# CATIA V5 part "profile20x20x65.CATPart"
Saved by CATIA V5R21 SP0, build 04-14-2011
Part number: 65
Bounding box of the stored display mesh (mm): x -24.289 to -4.289, y -1.335 to 18.665, z 0 to 65
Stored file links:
  C:\Users\2027.DESARCY-LEMIE30\Desktop\V15(20.03.2023)\profile20x20x65.CATPart
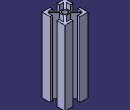
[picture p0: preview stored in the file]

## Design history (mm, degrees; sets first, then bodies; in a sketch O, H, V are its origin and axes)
Body1 (main body)
  Sketch1 on xy-plane, origin (0, 0, 0), H (1, 0, 0), V (0, 1, 0)
    point P1 (-17.2892, 11.6647)
    line L1 (-16.2892, 11.6647) -> (-12.2892, 11.6647)
    point P2 (-11.2892, 11.6647)
    line L2 (-11.2892, 10.6647) -> (-11.2892, 6.6647)
    point P3 (-11.2892, 5.6647)
    line L3 (-12.2892, 5.6647) -> (-16.2892, 5.6647)
    point P4 (-17.2892, 5.6647)
    line L4 (-17.2892, 6.6647) -> (-17.2892, 10.6647)
    point P5 (-24.2892, 18.6647)
    point P6 (-4.2892, 18.6647)
    point P7 (-4.2892, -1.3353)
    line L5 (-11.1892, 18.6647) -> (-11.1892, 16.6647)
    point P8 (-11.1892, 18.6647)
    point P10 (-11.1892, 18.6647)
    point P11 (-17.3892, 18.6647)
    line L6 (-17.3892, 18.6647) -> (-17.3892, 16.6647)
    point P12 (-17.3892, 18.6647)
    line L7 (-11.1892, 18.6647) -> (-4.2892, 18.6647)
    point P14 (-11.1892, 18.6647)
    point P15 (-4.2892, 18.6647)
    point P16 (-11.1892, -1.3353)
    point P17 (-17.3892, -1.3353)
    line L8 (-17.3892, -1.3353) -> (-17.3892, 0.6647)
    point P18 (-17.3892, -1.3353)
    line L9 (-11.1892, -1.3353) -> (-11.1892, 0.6647)
    point P20 (-11.1892, -1.3353)
    line L10 (-24.2892, -1.3353) -> (-17.3892, -1.3353)
    point P22 (-24.2892, -1.3353)
    point P23 (-17.3892, -1.3353)
    line L11 (-11.1892, -1.3353) -> (-4.2892, -1.3353)
    point P24 (-11.1892, -1.3353)
    point P25 (-4.2892, -1.3353)
    line L12 (-24.2892, 18.6647) -> (-17.3892, 18.6647)
    point P26 (-24.2892, 18.6647)
    point P27 (-17.3892, 18.6647)
    point P28 (-4.2892, 5.5647)
    point P29 (-4.2892, 11.7647)
    line L13 (-6.2892, 11.7647) -> (-4.2892, 11.7647)
    point P31 (-4.2892, 11.7647)
    line L14 (-4.2892, 5.5647) -> (-6.2892, 5.5647)
    point P32 (-4.2892, 5.5647)
    point P34 (-24.2892, 5.5647)
    point P35 (-24.2892, 11.7647)
    line L15 (-24.2892, 11.7647) -> (-22.2892, 11.7647)
    point P36 (-24.2892, 11.7647)
    line L16 (-24.2892, 5.5647) -> (-22.2892, 5.5647)
    point P38 (-24.2892, 5.5647)
    line L17 (-4.2892, 18.6647) -> (-4.2892, 11.7647)
    point P40 (-4.2892, 18.6647)
    point P41 (-4.2892, 11.7647)
    line L18 (-24.2892, 18.6647) -> (-24.2892, 11.7647)
    point P42 (-24.2892, 18.6647)
    point P43 (-24.2892, 11.7647)
    line L19 (-24.2892, -1.3353) -> (-24.2892, 5.5647)
    point P44 (-24.2892, -1.3353)
    point P45 (-24.2892, 5.5647)
    line L20 (-4.2892, -1.3353) -> (-4.2892, 5.5647)
    point P46 (-4.2892, -1.3353)
    point P47 (-4.2892, 5.5647)
    line L21 (-22.2892, 5.5647) -> (-22.2892, 1.6647)
    line L22 (-21.2892, 0.6647) -> (-17.3892, 0.6647)
    line L23 (-6.2892, 5.5647) -> (-6.2892, 1.6647)
    line L24 (-11.1892, 0.6647) -> (-7.2892, 0.6647)
    line L25 (-11.1892, 16.6647) -> (-7.2892, 16.6647)
    line L26 (-6.2892, 15.6647) -> (-6.2892, 11.7647)
    line L27 (-17.3892, 16.6647) -> (-21.2892, 16.6647)
    line L28 (-22.2892, 15.6647) -> (-22.2892, 11.7647)
    point P48 (-16.2892, 11.6647)
    point P49 (-17.2892, 10.6647)
    point P50 (-17.2892, 6.6647)
    point P52 (-11.2892, 6.6647)
    point P53 (-11.2892, 10.6647)
    point P54 (-12.2892, 11.6647)
    point P55 (-12.2892, 5.6647)
    line L29 (-16.2892, 11.6647) -> (-21.2892, 16.6647)
    line L30 (-17.2892, 10.6647) -> (-22.2892, 15.6647)
    line L31 (-12.2892, 11.6647) -> (-7.2892, 16.6647)
    line L32 (-16.2892, 5.6647) -> (-21.2892, 0.6647)
    line L33 (-17.2892, 6.6647) -> (-22.2892, 1.6647)
    line L34 (-12.2892, 5.6647) -> (-7.2892, 0.6647)
    line L35 (-11.2892, 6.6647) -> (-6.2892, 1.6647)
    line L36 (-11.2892, 10.6647) -> (-6.2892, 15.6647)
    length L5 = 2
    distance P10 P6 = 6.9
    length L6 = 2
    length L8 = 2
    length L9 = 2
    distance P7 P28 = 6.9
    distance P6 P29 = 6.9
    length L13 = 2
    length L14 = 2
    length L15 = 2
    distance P5 P42 = 0
    length L11 = 6.9
    distance P46 P7 = 0
    distance P1 P48 = 1
    distance P49 P1 = 1
    distance P4 P50 = 1
    distance P54 P2 = 1
    distance P2 P3 = 6
    distance P1 P2 = 6
    horizontal: L1 H, L3 H, L7 H, L10 H, L11 H, L12 H, L13 H, L14 H, L15 H, L16 H, L22 H, L24 H, L25 H, L27 H
    vertical: L2 V, L4 V, L5 V, L6 V, L8 V, L9 V, L17 V, L18 V, L19 V, L20 V, L21 V, L23 V, L26 V, L28 V
    coincidence: P10 P8, P11 P12, P6 P15, P8 P14, P16 L5, P17 L6, P17 P18, P16 P20, P23 L8, P24 L9, P20 P24, P27 L6, P5 P26, P29 P31, P28 P32, P34 L14, P35 L13, P34 P38, P35 P36, P40 L7, P41 L13, P6 P40, P42 L7, P43 L13, P44 L11, P45 L14, P38 P45, P46 L11, P47 L14, P49 L4, P50 L4, P52 L2, P53 L2, P55 L3, P22 P44, P25 P46
    fix: P34, P12, P5, P36, P55
  Pad1: profile Sketch1, direction (0, 0, 1), length 65
  Sketch2 on end face of Pad1, origin (0, 0, 65), H (1, 0, 0), V (0, 1, 0)
    circle A1 centre (-14.2892, 8.6647) radius 2.5
    point P1 (-14.2892, 8.6647)
    reference projected line E1 (-12.2892, 11.6647) -> (-16.2892, 11.6647) from edge [face of Pad1 from Sketch1.L1 | end face of Pad1]
    reference projected line E2 (-11.2892, 6.6647) -> (-11.2892, 10.6647) from edge [face of Pad1 from Sketch1.L2 | end face of Pad1]
    radius A1 = 2.5
    distance P1 E1 = 3
    distance P1 E2 = 3
  Pocket1: profile Sketch2, direction (0, 0, -1), length 105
